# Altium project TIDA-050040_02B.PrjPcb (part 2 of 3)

## Sheet TIDA-050040_Battery.SchDoc
size 431 x 279 mm; Date: Not shown in title block; ApprovedBy: Not shown in title block; CheckedBy: Not shown in title block; Author: Not shown in title block; CompanyName: Not shown in title block; Engineer: Not shown in title block; Organization: Not shown in title block; Address1: Not shown in title block; Address2: Not shown in title block; Address3: Not shown in title block; Address4: Not shown in title block; DocumentNumber: 1; Revision: Use project parameter SCH_Rev; SheetNumber: 2; SheetTotal: 3; PageSetup: Record=PageOptions¦CenterHorizontal=True¦CenterVertical=True¦PrintScale=1.00¦XCorrection=1.00¦YCorrection=1.00¦PrintKind=0¦BorderSize=5000000¦LeftOffset=0¦BottomOffset=0¦Orientation=2¦PaperLength=1000¦PaperWidth=1000¦Scale=100¦PaperSource=15¦PrintQuality=600¦MediaType=1¦DitherType=10¦PaperKind=Letter¦PrintScaleMode=1
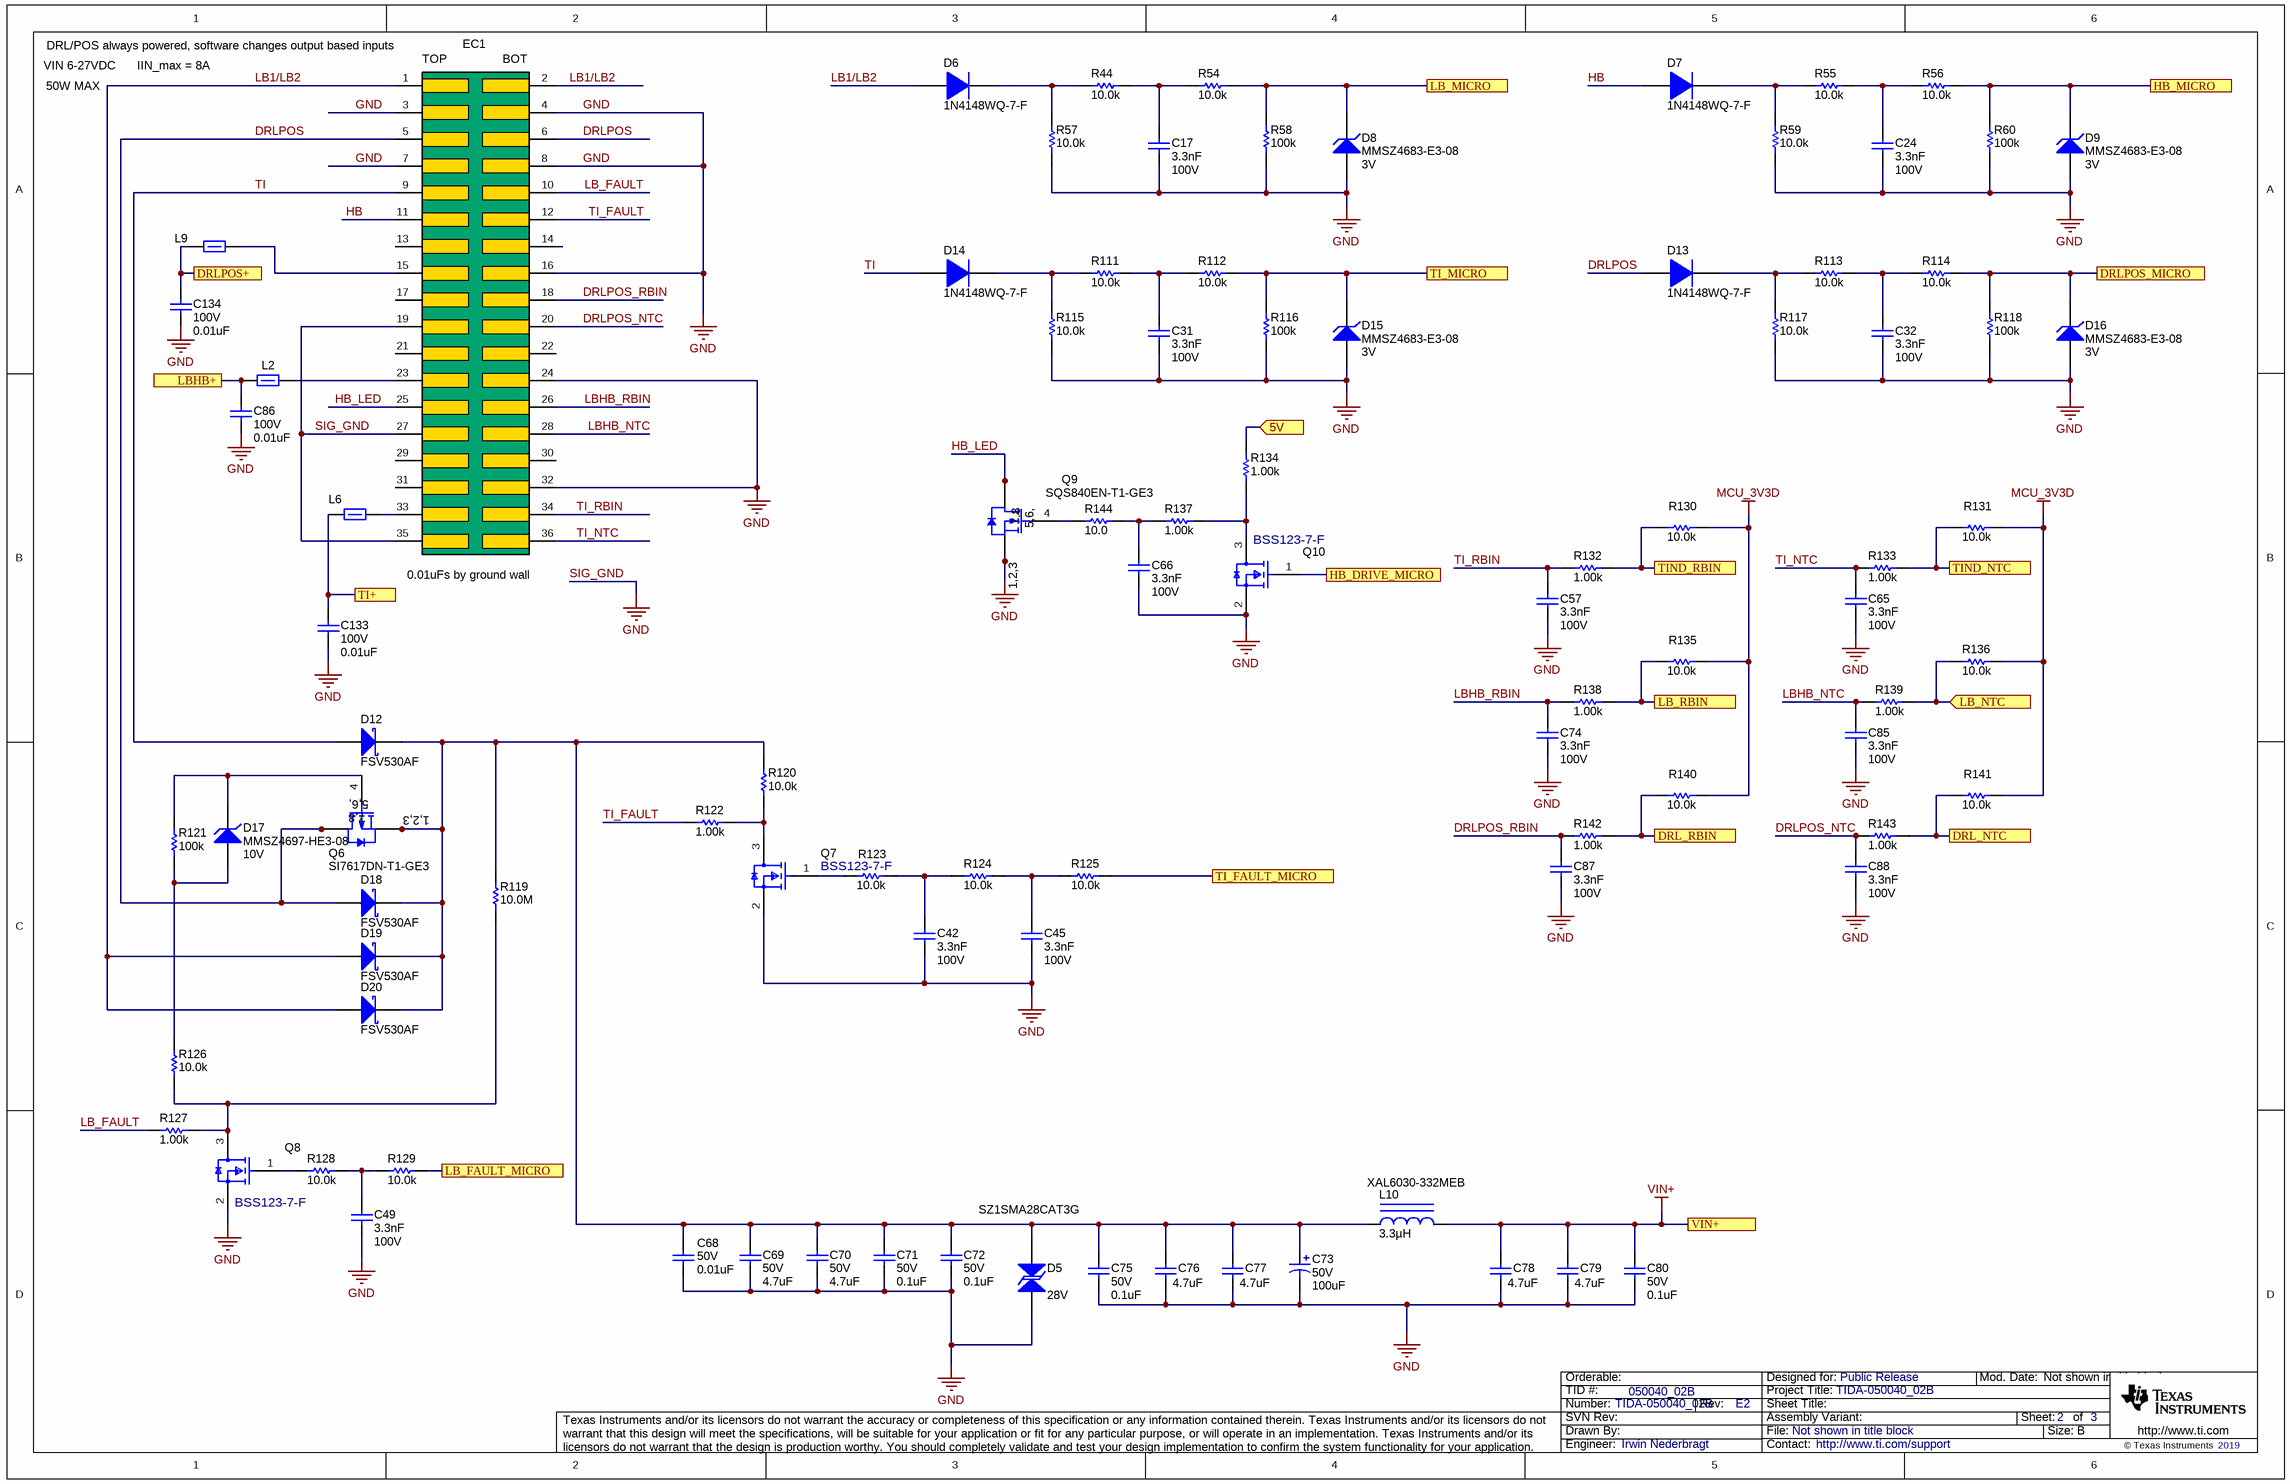
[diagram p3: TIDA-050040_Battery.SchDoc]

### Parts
C17  Cap_F: 3.3nF  VDC_V: 100V  [0603]  (hidden comment: GCM188R72A332KA37D)
C24  Cap_F: 3.3nF  VDC_V: 100V  [0603]  (hidden comment: GCM188R72A332KA37D)
C31  Cap_F: 3.3nF  VDC_V: 100V  [0603]  (hidden comment: GCM188R72A332KA37D)
C32  Cap_F: 3.3nF  VDC_V: 100V  [0603]  (hidden comment: GCM188R72A332KA37D)
C42  Cap_F: 3.3nF  VDC_V: 100V  [0603]  (hidden comment: GCM188R72A332KA37D)
C45  Cap_F: 3.3nF  VDC_V: 100V  [0603]  (hidden comment: GCM188R72A332KA37D)
C49  Cap_F: 3.3nF  VDC_V: 100V  [0603]  (hidden comment: GCM188R72A332KA37D)
C57  Cap_F: 3.3nF  VDC_V: 100V  [0603]  (hidden comment: GCM188R72A332KA37D)
C65  Cap_F: 3.3nF  VDC_V: 100V  [0603]  (hidden comment: GCM188R72A332KA37D)
C66  Cap_F: 3.3nF  VDC_V: 100V  [0603]  (hidden comment: GCM188R72A332KA37D)
C68  VDC_V: 50V  ValueDisplayed: 0.01uF  [0603]  (hidden comment: GCM188R71H103KA37D)
C69  VDC_V: 50V  ValueDisplayed: 4.7uF  [1206_180]  (hidden comment: C3216X7R1H475K160AC)
C70  VDC_V: 50V  ValueDisplayed: 4.7uF  [1206_180]  (hidden comment: C3216X7R1H475K160AC)
C71  VDC_V: 50V  ValueDisplayed: 0.1uF  [0805_HV]  (hidden comment: C0805C104K5RACAUTO)
C72  VDC_V: 50V  ValueDisplayed: 0.1uF  [0805_HV]  (hidden comment: C0805C104K5RACAUTO)
C73  VDC_V: 50V  ValueDisplayed: 100uF  [SM_RADIAL_F]  (hidden comment: EEE-FK1H101P)
C74  Cap_F: 3.3nF  VDC_V: 100V  [0603]  (hidden comment: GCM188R72A332KA37D)
C75  VDC_V: 50V  ValueDisplayed: 0.1uF  [0805_HV]  (hidden comment: C0805C104K5RACAUTO)
C76  ValueDisplayed: 4.7uF  [1206_180]  (hidden comment: C3216X7R1H475K160AC)
C77  ValueDisplayed: 4.7uF  [1206_180]  (hidden comment: C3216X7R1H475K160AC)
C78  ValueDisplayed: 4.7uF  [1206_180]  (hidden comment: C3216X7R1H475K160AC)
C79  ValueDisplayed: 4.7uF  [1206_180]  (hidden comment: C3216X7R1H475K160AC)
C80  VDC_V: 50V  ValueDisplayed: 0.1uF  [0805_HV]  (hidden comment: C0805C104K5RACAUTO)
C85  Cap_F: 3.3nF  VDC_V: 100V  [0603]  (hidden comment: GCM188R72A332KA37D)
C86  VDC_V: 100V  ValueDisplayed: 0.01uF  [0603]  (hidden comment: GRM188R72A103KA01D)
C87  Cap_F: 3.3nF  VDC_V: 100V  [0603]  (hidden comment: GCM188R72A332KA37D)
C88  Cap_F: 3.3nF  VDC_V: 100V  [0603]  (hidden comment: GCM188R72A332KA37D)
C133  VDC_V: 100V  ValueDisplayed: 0.01uF  [0603]  (hidden comment: GRM188R72A103KA01D)
C134  VDC_V: 100V  ValueDisplayed: 0.01uF  [0603]  (hidden comment: GRM188R72A103KA01D)
D5  SZ1SMA28CAT3G  value 28V  [SMA_Bi]
D6  1N4148WQ-7-F  [SOD-123]
D7  1N4148WQ-7-F  [SOD-123]
D8  MMSZ4683-E3-08  value 3V  [SOD-123]
D9  MMSZ4683-E3-08  value 3V  [SOD-123]
D12  FSV530AF  [SMAF]
D13  1N4148WQ-7-F  [SOD-123]
D14  1N4148WQ-7-F  [SOD-123]
D15  MMSZ4683-E3-08  value 3V  [SOD-123]
D16  MMSZ4683-E3-08  value 3V  [SOD-123]
D17  MMSZ4697-HE3-08  value 10V  [SOD-123]
D18  FSV530AF  [SMAF]
D19  FSV530AF  [SMAF]
D20  FSV530AF  [SMAF]
EC1  EDGE_CONN_EBC18DCWN-S371  [Sullins_EDGE_CONN_EBC18DCWN-S371]  (value not drawn)  (no BOM)
L2  742792012  [0805_HV]  (value not drawn)
L6  742792012  [0805_HV]  (value not drawn)
L9  742792012  [0805_HV]  (value not drawn)
L10  ValueDisplayed: 3.3µH  [XAL6030]  (hidden comment: XAL6030-332MEB)
Q6  SI7617DN-T1-GE3  [PowerPAK_1212-8]
Q7  BSS123-7-F  [FP-BSS123-7-F_SOT23-MFG]
Q8  BSS123-7-F  [FP-BSS123-7-F_SOT23-MFG]
Q9  SQS840EN-T1-GE3  [PowerPAK_1212-8]
Q10  BSS123-7-F  [FP-BSS123-7-F_SOT23-MFG]
R44  ValueDisplayed: 10.0k  [0603]  (hidden comment: CRCW060310K0FKEA)
R54  ValueDisplayed: 10.0k  [0603]  (hidden comment: CRCW060310K0FKEA)
R55  ValueDisplayed: 10.0k  [0603]  (hidden comment: CRCW060310K0FKEA)
R56  ValueDisplayed: 10.0k  [0603]  (hidden comment: CRCW060310K0FKEA)
R57  ValueDisplayed: 10.0k  [0603]  (hidden comment: CRCW060310K0FKEA)
R58  ValueDisplayed: 100k  [0603]  (hidden comment: CRCW0603100KFKEA)
R59  ValueDisplayed: 10.0k  [0603]  (hidden comment: CRCW060310K0FKEA)
R60  ValueDisplayed: 100k  [0603]  (hidden comment: CRCW0603100KFKEA)
R111  ValueDisplayed: 10.0k  [0603]  (hidden comment: CRCW060310K0FKEA)
R112  ValueDisplayed: 10.0k  [0603]  (hidden comment: CRCW060310K0FKEA)
R113  ValueDisplayed: 10.0k  [0603]  (hidden comment: CRCW060310K0FKEA)
R114  ValueDisplayed: 10.0k  [0603]  (hidden comment: CRCW060310K0FKEA)
R115  ValueDisplayed: 10.0k  [0603]  (hidden comment: CRCW060310K0FKEA)
R116  ValueDisplayed: 100k  [0603]  (hidden comment: CRCW0603100KFKEA)
R117  ValueDisplayed: 10.0k  [0603]  (hidden comment: CRCW060310K0FKEA)
R118  ValueDisplayed: 100k  [0603]  (hidden comment: CRCW0603100KFKEA)
R119  ValueDisplayed: 10.0M  [0603]  (hidden comment: RC0603FR-0710ML)
R120  ValueDisplayed: 10.0k  [0603]  (hidden comment: CRCW060310K0FKEA)
R121  ValueDisplayed: 100k  [0603]  (hidden comment: CRCW0603100KFKEA)
R122  ValueDisplayed: 1.00k  [0603]  (hidden comment: CRCW06031K00FKEA)
R123  ValueDisplayed: 10.0k  [0603]  (hidden comment: CRCW060310K0FKEA)
R124  ValueDisplayed: 10.0k  [0603]  (hidden comment: CRCW060310K0FKEA)
R125  ValueDisplayed: 10.0k  [0603]  (hidden comment: CRCW060310K0FKEA)
R126  ValueDisplayed: 10.0k  [0603]  (hidden comment: CRCW060310K0FKEA)
R127  ValueDisplayed: 1.00k  [0603]  (hidden comment: CRCW06031K00FKEA)
R128  ValueDisplayed: 10.0k  [0603]  (hidden comment: CRCW060310K0FKEA)
R129  ValueDisplayed: 10.0k  [0603]  (hidden comment: CRCW060310K0FKEA)
R130  ValueDisplayed: 10.0k  [0603]  (hidden comment: CRCW060310K0FKEA)
R131  ValueDisplayed: 10.0k  [0603]  (hidden comment: CRCW060310K0FKEA)
R132  ValueDisplayed: 1.00k  [0603]  (hidden comment: CRCW06031K00FKEA)
R133  ValueDisplayed: 1.00k  [0603]  (hidden comment: CRCW06031K00FKEA)
R134  ValueDisplayed: 1.00k  [0603]  (hidden comment: CRCW06031K00FKEA)
R135  ValueDisplayed: 10.0k  [0603]  (hidden comment: CRCW060310K0FKEA)
R136  ValueDisplayed: 10.0k  [0603]  (hidden comment: CRCW060310K0FKEA)
R137  ValueDisplayed: 1.00k  [0603]  (hidden comment: CRCW06031K00FKEA)
R138  ValueDisplayed: 1.00k  [0603]  (hidden comment: CRCW06031K00FKEA)
R139  ValueDisplayed: 1.00k  [0603]  (hidden comment: CRCW06031K00FKEA)
R140  ValueDisplayed: 10.0k  [0603]  (hidden comment: CRCW060310K0FKEA)
R141  ValueDisplayed: 10.0k  [0603]  (hidden comment: CRCW060310K0FKEA)
R142  ValueDisplayed: 1.00k  [0603]  (hidden comment: CRCW06031K00FKEA)
R143  ValueDisplayed: 1.00k  [0603]  (hidden comment: CRCW06031K00FKEA)
R144  ValueDisplayed: 10.0  [0603]  (hidden comment: CRCW060310R0FKEA)

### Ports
5V, DRL_NTC, DRL_RBIN, DRLPOS+, DRLPOS_MICRO, HB_DRIVE_MICRO, HB_MICRO, LB_FAULT_MICRO, LB_MICRO, LB_NTC, LB_RBIN, LBHB+, TI+, TI_FAULT_MICRO, TI_MICRO, TIND_NTC, TIND_RBIN, VIN+

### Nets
5V: R134.2 ; port 5V
GND: C17.2 C24.2 C31.2 C32.2 C42.2 C45.2 C49.2 C57.2 C65.2 C66.2 C68.2 C69.2 C70.2 C71.2 C72.2 C73.2(-) C74.2 C75.2 C76.2 C77.2 C78.2 C79.2 C80.2 C85.2 C86.2 C87.2 C88.2 C133.2 C134.2 D5.1 D8.2(A) D9.2(A) D15.2(A) D16.2(A) EC1.3 EC1.4 EC1.7 EC1.8 EC1.16 EC1.19 EC1.24 EC1.27 EC1.32 EC1.35 Q7.2(S) Q8.2(S) Q9.1(S) Q9.2(S) Q9.3(S) Q10.2(S) R57.1 R58.1 R59.1 R60.1 R115.1 R116.1 R117.1 R118.1  [also labelled SIG_GND]
MCU_3V3D: R130.2 R131.2 R135.2 R136.2 R140.2 R141.2
VIN+: C78.1 C79.1 C80.1 L10.2 ; port VIN+  [project net VIN]
DRL_NTC: R141.1 R143.2 ; port DRL_NTC
DRLPOS: D13.2(A) D18.2(A) EC1.5 EC1.6 Q6.5(D) Q6.6(D) Q6.7(D) Q6.8(D) Q6.9(D)
DRLPOS+: C134.1 L9.1 ; port DRLPOS+
DRLPOS_MICRO: D16.1(K) R114.2 R118.2 ; port DRLPOS_MICRO
DRLPOS_NTC: C88.1 EC1.20 R143.1
DRLPOS_RBIN: C87.1 EC1.18 R142.1
HB: D7.2(A) EC1.11
HB_DRIVE_MICRO: Q10.1(G) ; port HB_DRIVE_MICRO
HB_LED: EC1.25 Q9.5(D) Q9.6(D) Q9.7(D) Q9.8(D) Q9.9(D)
HB_MICRO: D9.1(K) R56.2 R60.2 ; port HB_MICRO
LB1/LB2: D6.2(A) D19.2(A) D20.2(A) EC1.1 EC1.2
LB_FAULT: EC1.10 R127.1
LB_FAULT_MICRO: R129.2 ; port LB_FAULT_MICRO
LB_MICRO: D8.1(K) R54.2 R58.2 ; port LB_MICRO
LB_NTC: R136.1 R139.2 ; port LB_NTC
LBHB+: C86.1 L2.1 ; port LBHB+
LBHB_NTC: C85.1 EC1.28 R139.1
LBHB_RBIN: C74.1 EC1.26 R138.1
PD5: R135.1 R138.2 ; port LB_RBIN
PD6: R130.1 R132.2 ; port TIND_RBIN
PD7: R140.1 R142.2 ; port DRL_RBIN
TI: D12.2(A) D14.2(A) EC1.9
TI+: C133.1 L6.1 ; port TI+
TI_FAULT: EC1.12 R122.1
TI_FAULT_MICRO: R125.2 ; port TI_FAULT_MICRO
TI_MICRO: D15.1(K) R112.2 R116.2 ; port TI_MICRO
TI_NTC: C65.1 EC1.36 R133.1
TI_RBIN: C57.1 EC1.34 R132.1
TIND_NTC: R131.1 R133.2 ; port TIND_NTC
NetC17_1: C17.1 R44.2 R54.1
NetC24_1: C24.1 R55.2 R56.1
NetC31_1: C31.1 R111.2 R112.1
NetC32_1: C32.1 R113.2 R114.1
NetC42_1: C42.1 R123.2 R124.1
NetC45_1: C45.1 R124.2 R125.1
NetC49_1: C49.1 R128.2 R129.1
NetC66_1: C66.1 R137.1 R144.2
NetC68_1: C68.1 C69.1 C70.1 C71.1 C72.1 C73.1(+) C75.1 C76.1 C77.1 D5.2 D12.1(K) D18.1(K) D19.1(K) D20.1(K) L10.1 Q6.1(S) Q6.2(S) Q6.3(S) R119.2 R120.2
NetD6_1: D6.1(K) R44.1 R57.2
NetD7_1: D7.1(K) R55.1 R59.2
NetD13_1: D13.1(K) R113.1 R117.2
NetD14_1: D14.1(K) R111.1 R115.2
NetD17_1: D17.1(K) Q6.4(G) R121.2
NetD17_2: D17.2(A) R121.1 R126.2
NetEC1_15: EC1.15 L9.2
NetEC1_23: EC1.23 L2.2
NetEC1_33: EC1.33 L6.2
NetQ7_1: Q7.1(G) R123.1
NetQ7_3: Q7.3(D) R120.1 R122.2
NetQ8_1: Q8.1(G) R128.1
NetQ8_3: Q8.3(D) R119.1 R126.1 R127.2
NetQ9_4: Q9.4(G) R144.1
NetQ10_3: Q10.3(D) R134.1 R137.2

Not connected (* = marked no-connect by the designer): EC1 13 14 17 21 22 29 30 31

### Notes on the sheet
- 50W MAX
- VIN 6-27VDC
- IIN_max = 8A
- (near EC1) DRL/POS always powered, software changes output based inputs
- (near EC1) 0.01uFs by ground wall

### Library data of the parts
C17 C24 C31 C32 C42 C45 C49 C57 C65 C66 C74 C85 C87 C88 = CMP-0007148-4: CAP, CERM, 3300 pF, 100 V, +/- 10%, X7R, AEC-Q200 Grade 1, 0603; Manufacturer: MuRata; TaMin_C: -55°C; Polarized: N; SizeAreaWB_mm2: 4.68; Value1: Unknown; U/M: EA; Value: 3300pF; TaMax_C: 125°C; SizeZ_mm: 1; SizeX_mm: 1.6; SizeY_mm: 0.8; SizeArea_mm2: 1.28; CompType: Capacitor; AEC Qualified: Y; AEC Category: Q200
C68 = CMP-0007143-4: CAP, CERM, 0.01 uF, 50 V, +/- 10%, X7R, AEC-Q200 Grade 1, 0603; Manufacturer: MuRata; TaMin_C: -55°C; Polarized: N; SizeAreaWB_mm2: 4.68; Value1: Unknown; U/M: EA; Value: 0.01uF; TaMax_C: 125°C; SizeZ_mm: 1; SizeX_mm: 1.6; SizeY_mm: 0.8; SizeArea_mm2: 1.28; CompType: Capacitor; AEC Qualified: Y; Cap_F: 10nF; AEC Category: Q200
C69 C70 = CMP-0008702-2: CAP, CERM, 4.7 uF, 50 V, +/- 10%, X7R, 1206; Manufacturer: TDK; TaMin_C: -55°C; ESR_ohm: 3.158m; Polarized: N; SizeAreaWB_mm2: 10.92; Value1: 0.003158 ohm; U/M: EA; Value: 4.7uF; TaMax_C: 125°C; SizeZ_mm: 1.8; SizeX_mm: 3.2; SizeY_mm: 1.6; SizeArea_mm2: 5.12; Cap_F: 4.7µF; IRMS_A: 4.08379A; AEC Category: Q200
C71 C72 C75 C80 = CMP-0007725-2: CAP, CERM, 0.1 uF, 50 V, +/- 10%, X7R, AEC-Q200 Grade 0, 0805; Manufacturer: Kemet; TaMin_C: -55°C; Polarized: N; SizeAreaWB_mm2: 6.75; Value1: Unknown; U/M: EA; Value: 0.1uF; TaMax_C: 125°C; SizeZ_mm: 1.45; SizeX_mm: 2; SizeY_mm: 1.25; Cap_Case: 0805; SizeArea_mm2: 2.5; CompType: Capacitor; AEC Qualified: Y; Cap_F: 100nF; AEC Grade: 0; AEC Category: Q200
C73 = CMP-0011177-2: CAP, AL, 100 uF, 50 V, +/- 20%, 0.34 ohm, AEC-Q200 Grade 2, SMD; Manufacturer: Panasonic; TaMin_C: -55°C; ESR_ohm: 3.4d; Polarized: Y; SizeAreaWB_mm2: 123.6; U/M: EA; Value: 100uF; TaMax_C: 105°C; SizeZ_mm: 10.2; SizeX_mm: 10; SizeY_mm: 8.3; Cap_Case: F; SizeArea_mm2: 83; CompType: Capacitor; Cap_F: 100µF; IRMS_A: 3.5dA; AEC Grade: 2; AEC Category: Q200
C76-C79 = CMP-0008702-2: CAP, CERM, 4.7 uF, 50 V, +/- 10%, X7R, 1206; Manufacturer: TDK; TaMin_C: -55°C; ESR_ohm: 3.158m; Polarized: N; SizeAreaWB_mm2: 10.92; Value1: 0.003158 ohm; U/M: EA; Value: 4.7uF; TaMax_C: 125°C; SizeZ_mm: 1.8; SizeX_mm: 3.2; SizeY_mm: 1.6; Value2: 50V; SizeArea_mm2: 5.12; CompType: Capacitor; Cap_F: 4.7µF; IRMS_A: 4.08379A; AEC Category: Q200
C86 C133 C134 = CMP-0007468-5: CAP, CERM, 0.01 uF, 100 V, +/- 10%, X7R, 0603; Manufacturer: MuRata; TaMin_C: -55°C; Polarized: N; SizeAreaWB_mm2: 4.68; Value1: Unknown; U/M: EA; Value: 0.01uF; TaMax_C: 125°C; SizeZ_mm: 1; SizeX_mm: 1.6; SizeY_mm: 0.8; SizeArea_mm2: 1.28; CompType: Capacitor; Cap_F: 10nF; AEC Category: Q200
D5 = CMP-0085086-1: Diode, TVS, Bi, 28 V, 45.4 Vc, 400 W, 8.8 A, AEC-Q101, SMA (non-polarized); Manufacturer: Littelfuse; SizeX_mm: 5.075; Value1: 45.4V; SizeAreaWB_mm2: 32.368125; SizeZ_mm: 2.65; Vbr_Max: 34.37V; Ipp: 8.8A; AEC Category: Q101; Vbr_Min: 31.1V; SizeArea_mm2: 13.068125; AEC Qualified: Y; SizeY_mm: 2.575; Ppk: 400W; RJA_CperW: 250
D6 D7 D13 D14 = CMP-0750148-1: Diode, Switching, 100 V, 0.3 A, AEC-Q101, SOD-123; Manufacturer: Diodes Inc.; Value2: 1.25V; TJmax_C: 150°C; AEC Category: Q101; Value: 100V; SizeAreaWB_mm2: 13.095; SizeArea_mm2: 6.545; SizeX_mm: 3.85; AEC Qualified: Y; Io_A: 3dA; Value1: 0.3A; SizeZ_mm: 1.35; SizeY_mm: 1.7
D8 D9 D15 D16 = CMP-0077593-3: Diode, Zener, 3 V, 500 mW, SOD-123; Manufacturer: Vishay-Semiconductor; SizeAreaWB_mm2: 13.095; Value1: 0.5W; SizeArea_mm2: 6.545; AEC Category: Q101; SizeX_mm: 3.85; SizeY_mm: 1.7; AEC Qualified: N; Power_W: 500mW; RJA_CperW: 340; SizeZ_mm: 1.35
D12 D18-D20 = CMP-0028823-2: Diode, Schottky, 30 V, 5 A, AEC-Q101, SMAF; Manufacturer: Fairchild Semiconductor; Io_A: 5A; Vr_V: 30V; SizeY_mm: 2.5; Green_REACh: Incomplete; SizeArea_mm2: 11.75; SizeZ_mm: 1; AEC Category: Q101; Vf_V: 5.4dV; AEC Qualified: Y; SizeAreaWB_mm2: 19.95; Green_Lifecycle: Not Set; SizeX_mm: 4.7; Value: 30V; Value2: 0.54V; TJmax_C: 150°C
D17 = CMP-0077570-3: Diode, Zener, 10 V, 500 mW, AEC-Q101, SOD-123; Manufacturer: Vishay-Semiconductor; SizeX_mm: 3.85; Power_W: 500mW; RJA_CperW: 340; SizeArea_mm2: 6.545; SizeAreaWB_mm2: 13.095; SizeY_mm: 1.7; AEC Category: Q101; Value1: 0.5W; SizeZ_mm: 1.35; AEC Qualified: Y
EC1 = CMP-0077097-2: Card Edge Footprint, 2.54mm, 18x2; Manufacturer: Sullins Connector Solutions; Pitch_mm: 2.54; CT: True; CNHeader: False
L2 L6 L9 = CMP-0003069-1: Ferrite Bead, 33 ohm @ 100 MHz, 4 A, 0805; Manufacturer: Wurth Elektronik; Ztyp@1GHz_Ohm: 65.242; ZTyp@100MHz_Ohm: 33; SizeAreaWB_mm2: 6.75; DCR_ohm: 8m; Value1: 0.008 ohm; Value: 33 ohm; Imax_A: 4A; SizeZ_mm: 1.45; SizeX_mm: 2; SizeY_mm: 1.25; SizeArea_mm2: 2.5
L10 = CMP-0061017-2: Inductor, Shielded, Composite, 3.3 µH, 8 A, 0.02081 ohm, AEC-Q200 Grade 1, SMD; Manufacturer: Coilcraft; Value: 3.3uH; Imax_A: 8A; Irms: 8A @ 40C rise; Isat: 12.2A @ 30% inductance drop; SizeAreaWB_mm2: 71.5616; SizeArea_mm2: 41.7216; SizeX_mm: 6.36; SizeY_mm: 6.56; SizeZ_mm: 3.1; AEC Category: Q200; AEC Qualified: Y; AEC Grade: 1; Green_Lifecycle: Not Set; Green_REACh: Incomplete
Q6 = CMP-0000123-4: MOSFET, P-CH, -30 V, -13.9 A, PowerPAK 1212; Manufacturer: Vishay-Siliconix; Alternate Manufacturer: None; SizeY_mm: 3.3; ChMode: Enhancement; IdsMax_A: -13.9A; Value1: 0.022; AEC Category: Q101; SizeZ_mm: 1.04; SizeAreaWB_mm2: 18.49; AEC Qualified: N; Value2: 20.5 nC; ChType: P; Rdson45_ohm: 0.0222; Value: -30V; Vgs_V: -25V; SizeArea_mm2: 10.89; QgTyp_nC: 20.5
Q7 Q8 Q10 = CMP-0087176-1: MOSFET N-CH 100V 170MA SOT23-3; Manufacturer: Diodes Incorporated; IdsMax_A: 1.7dA; Vgs_V: 20V; Symbol Name: SYM-BSS123-7-F; ChMode: False; AEC Qualified: No; SizeZ_mm: 1.1mm; Rdson45_ohm: 6
Q9 = CMP-0000752-2: MOSFET, N-CH, 40 V, 12 A, AEC-Q101, PowerPAK 1212; Alternate Manufacturer: None; Manufacturer: Vishay-Siliconix; SizeZ_mm: 1.04; ChType: N; Value2: 15 nC; Value1: 0; VdsMax_V: 40V; SizeX_mm: 3.3; Vgs_V: 20V; AEC Qualified: Y; Value: 40V; Rdson45_ohm: 0.03; SizeArea_mm2: 10.89; AEC Category: Q101; IdsMax_A: 12A; SizeAreaWB_mm2: 18.49; U/M: EA; QgTyp_nC: 15
R44 R54-R56 R111-R114 R123-R125 R128-R131 R135 R136 R140 R141 = CMP-0021998-4: RES, 10.0 k, 1%, 0.1 W, AEC-Q200 Grade 0, 0603; Manufacturer: Vishay-Dale; Power_W: 100mW; TempCo: 100 ppm/C; Value_Code: 10k0; Value: 10.0k; EIA_Code: E96; Res_ohm: 10k; SizeX_mm: 1.6; SizeY_mm: 0.8; SizeZ_mm: 1; Value2: 0.1W; SizeArea_mm2: 1.28; AEC Qualified: Y; VDC_V: 75V; AEC Category: Q200; AEC Grade: 0
R57 R59 R115 R117 R120 R126 = CMP-0021998-4: RES, 10.0 k, 1%, 0.1 W, AEC-Q200 Grade 0, 0603; Manufacturer: Vishay-Dale; Power_W: 100mW; TempCo: 100 ppm/C; Value_Code: 10k0; Value: 10.0k; EIA_Code: E96; Res_ohm: 10k; SizeX_mm: 1.6; SizeY_mm: 0.8; SizeZ_mm: 1; Value2: 0.1W; SizeArea_mm2: 1.28; CompType: Resistor; AEC Qualified: Y; VDC_V: 75V; AEC Category: Q200; AEC Grade: 0
R58 R60 R116 R118 R121 = CMP-0021990-4: RES, 100 k, 1%, 0.1 W, AEC-Q200 Grade 0, 0603; Manufacturer: Vishay-Dale; Power_W: 100mW; TempCo: 100 ppm/C; Value: 100k; EIA_Code: E96; SizeX_mm: 1.6; SizeY_mm: 0.8; SizeZ_mm: 1; Value2: 0.1W; SizeArea_mm2: 1.28; CompType: Resistor; AEC Qualified: Y; VDC_V: 75V; AEC Category: Q200; AEC Grade: 0
R119 = CMP-0022747-4: RES, 10.0 M, 1%, 0.1 W, 0603; Manufacturer: Yageo; Power_W: 100mW; TempCo: 100 ppm/C; Value_Code: 10M0; Value: 10.0Meg; EIA_Code: E96; Res_ohm: 10M; SizeX_mm: 1.6; SizeY_mm: 0.8; SizeZ_mm: 1; Value2: 0.1W; SizeArea_mm2: 1.28; CompType: Resistor; AEC Qualified: N; VDC_V: 75V; AEC Category: Q200; SizeAreaWB_mm2: 4.68
R122 R127 R132 R133 R137-R139 R142 R143 = CMP-0022109-5: RES, 1.00 k, 1%, 0.1 W, AEC-Q200 Grade 0, 0603; Manufacturer: Vishay-Dale; Power_W: 100mW; TempCo: 100 ppm/C; Value_Code: 1k00; Value: 1.00k; EIA_Code: E96; Res_ohm: 1k; SizeX_mm: 1.6; SizeY_mm: 0.8; SizeZ_mm: 1; Value2: 0.1W; SizeArea_mm2: 1.28; AEC Qualified: Y; VDC_V: 75V; AEC Category: Q200; AEC Grade: 0
R134 = CMP-0022109-5: RES, 1.00 k, 1%, 0.1 W, AEC-Q200 Grade 0, 0603; Manufacturer: Vishay-Dale; Power_W: 100mW; TempCo: 100 ppm/C; Value_Code: 1k00; Value: 1.00k; EIA_Code: E96; Res_ohm: 1k; SizeX_mm: 1.6; SizeY_mm: 0.8; SizeZ_mm: 1; Value2: 0.1W; SizeArea_mm2: 1.28; CompType: Resistor; AEC Qualified: Y; VDC_V: 75V; AEC Category: Q200; AEC Grade: 0
R144 = CMP-0022003-4: RES, 10.0, 1%, 0.1 W, AEC-Q200 Grade 0, 0603; Manufacturer: Vishay-Dale; Power_W: 100mW; TempCo: 100 ppm/C; Value_Code: 10R0; Value: 10.0; EIA_Code: E96; Res_ohm: 10; SizeX_mm: 1.6; SizeY_mm: 0.8; SizeZ_mm: 1; Value2: 0.1W; SizeArea_mm2: 1.28; AEC Qualified: Y; VDC_V: 75V; AEC Category: Q200; AEC Grade: 0

## Sheet TIDA-050040_MSP432E4x.SchDoc: Bucks 05-08
size 431 x 279 mm; Date: Not shown in title block; ApprovedBy: Not shown in title block; CheckedBy: Not shown in title block; Author: Not shown in title block; CompanyName: Not shown in title block; DrawnBy: Kerry Murphy; Engineer: Not shown in title block; Organization: Not shown in title block; Address1: Not shown in title block; Address2: Not shown in title block; Address3: Not shown in title block; Address4: Not shown in title block; DocumentNumber: 2; Revision: Use project parameter SCH_Rev; SheetNumber: 2; SheetTotal: 10; PageSetup: Record=PageOptions¦CenterHorizontal=True¦CenterVertical=True¦PrintScale=0.98¦XCorrection=1.00¦YCorrection=1.00¦PrintKind=0¦BorderSize=5000000¦LeftOffset=0¦BottomOffset=0¦Orientation=2¦PaperLength=1000¦PaperWidth=1000¦Scale=100¦PaperSource=15¦PrintQuality=600¦MediaType=1¦DitherType=10¦PrintScaleMode=1¦PaperKind=11 x 17¦PaperIndex=119
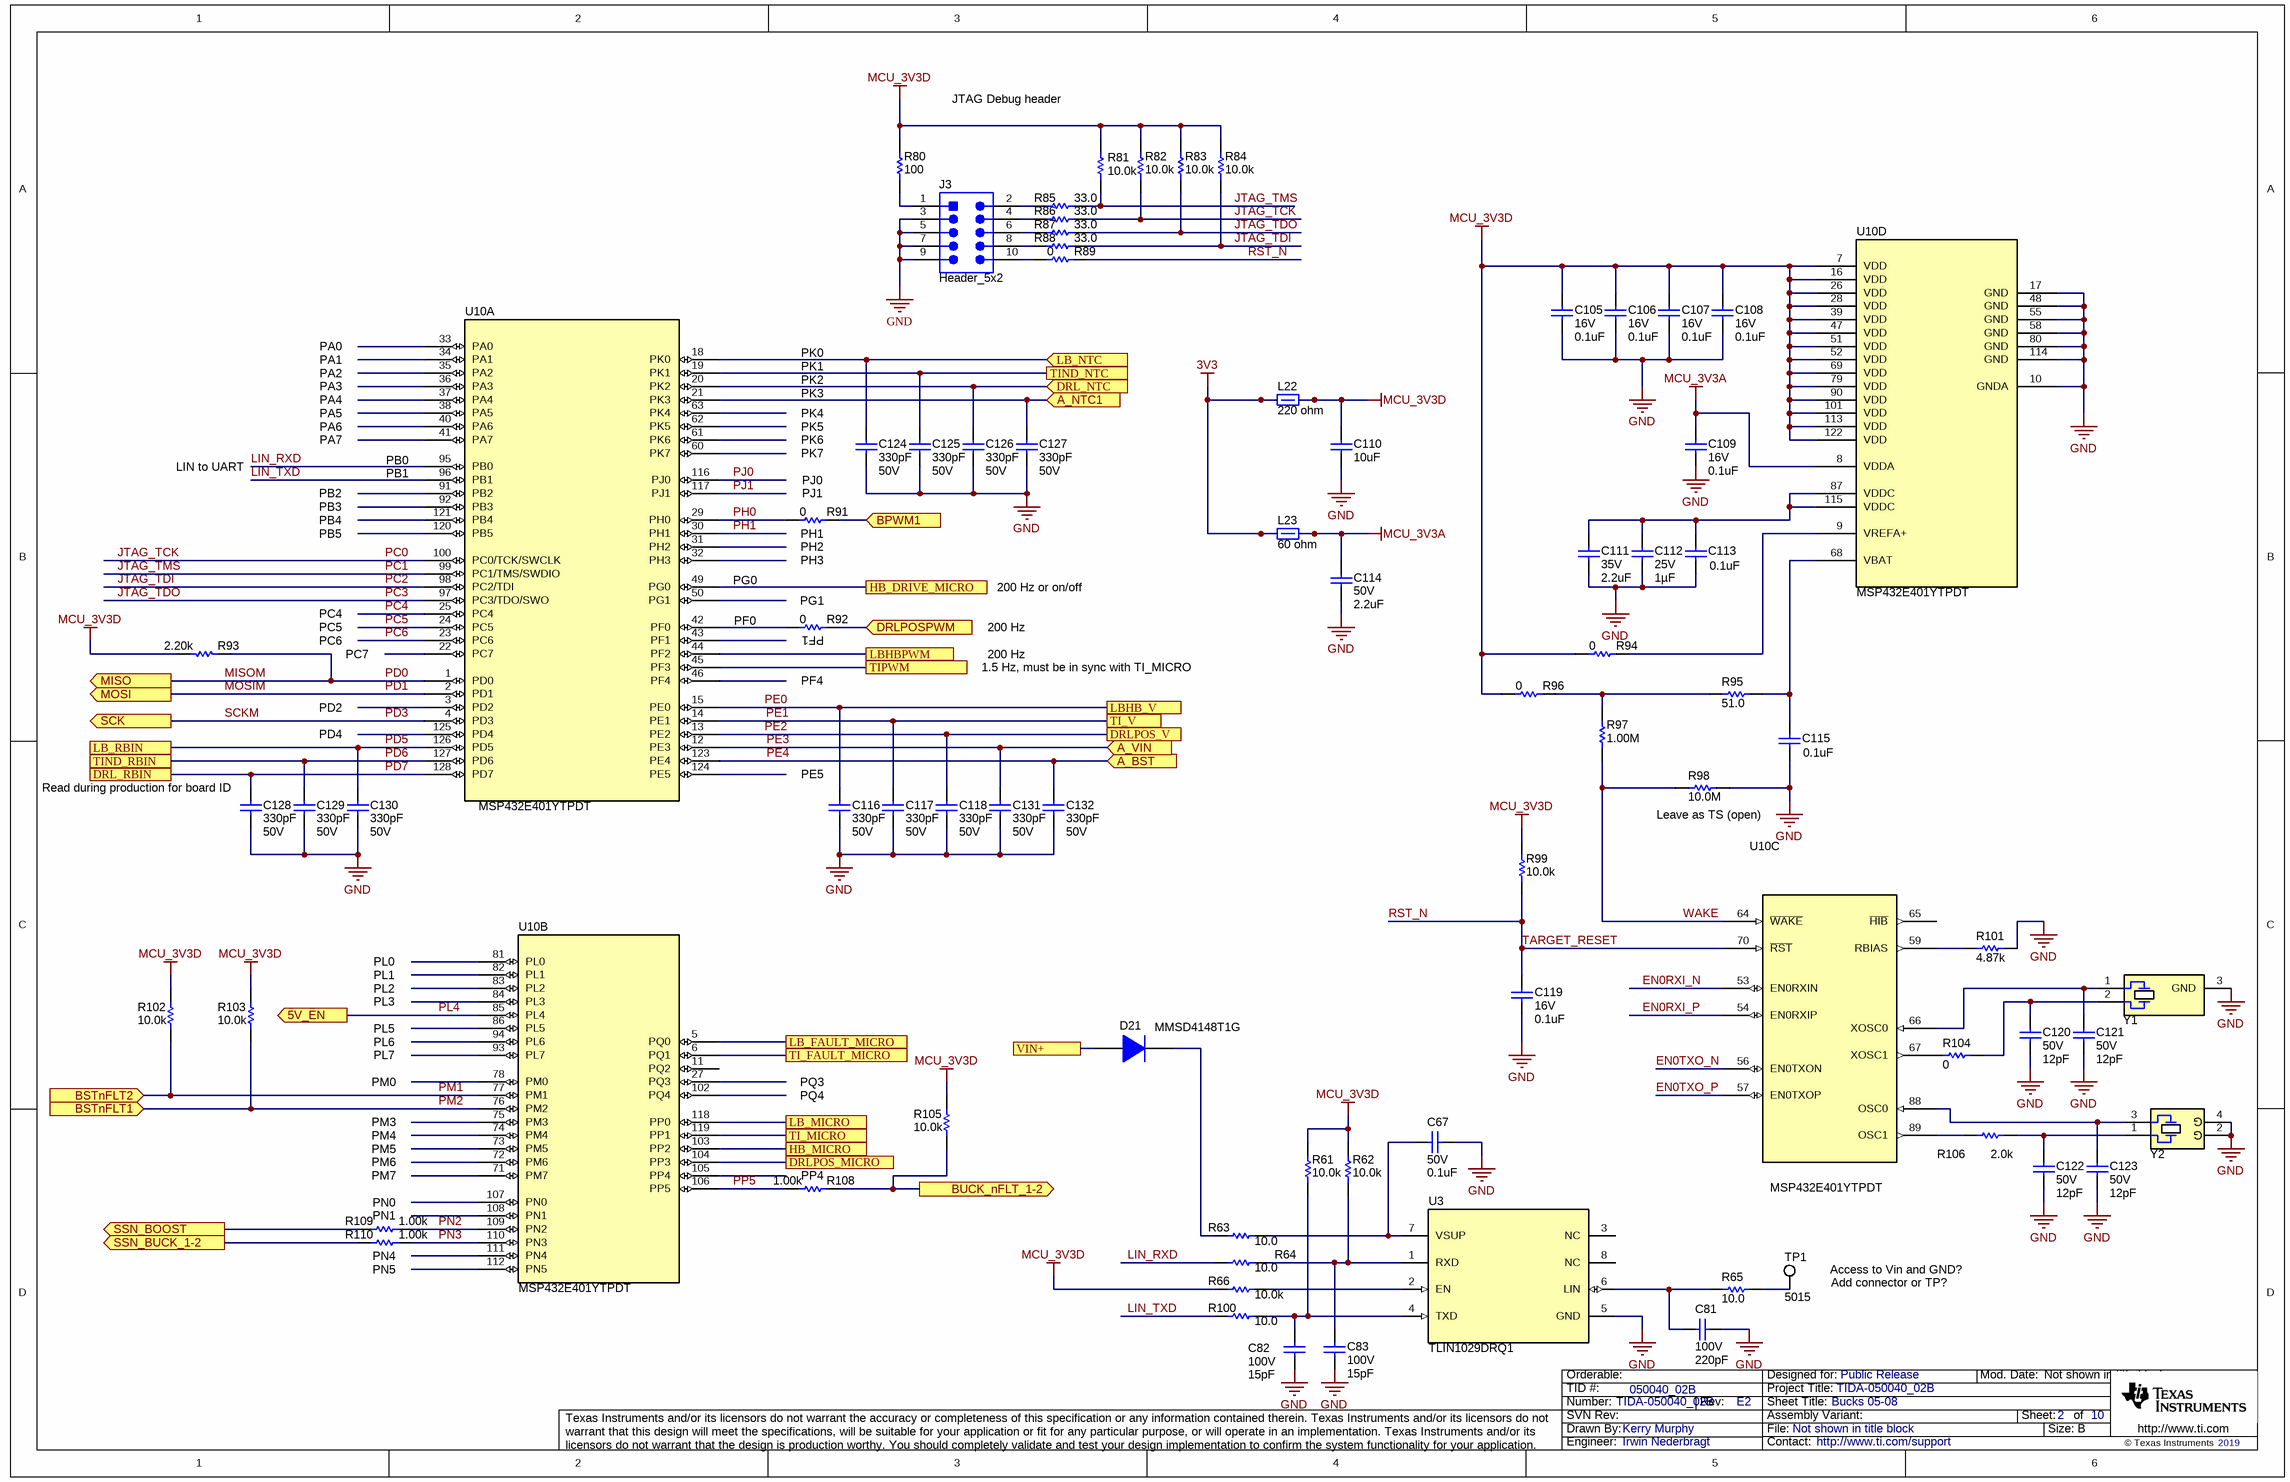
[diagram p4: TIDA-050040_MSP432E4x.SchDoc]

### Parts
C67  VDC_V: 50V  ValueDisplayed: 0.1uF  [0805_HV]  (hidden comment: C0805C104K5RACAUTO)
C81  VDC_V: 100V  ValueDisplayed: 220pF  [0603]  (hidden comment: GCM1885C2A221JA16D)
C82  VDC_V: 100V  ValueDisplayed: 15pF  [0603]  (hidden comment: GCM1885C2A150JA16D)
C83  VDC_V: 100V  ValueDisplayed: 15pF  [0603]  (hidden comment: GCM1885C2A150JA16D)
C105  VDC_V: 16V  ValueDisplayed: 0.1uF  [0402]  (hidden comment: GRM155R71C104KA88D)
C106  VDC_V: 16V  ValueDisplayed: 0.1uF  [0402]  (hidden comment: GRM155R71C104KA88D)
C107  VDC_V: 16V  ValueDisplayed: 0.1uF  [0402]  (hidden comment: GRM155R71C104KA88D)
C108  VDC_V: 16V  ValueDisplayed: 0.1uF  [0402]  (hidden comment: GRM155R71C104KA88D)
C109  VDC_V: 16V  ValueDisplayed: 0.1uF  [0402]  (hidden comment: GRM155R71C104KA88D)
C110  ValueDisplayed: 10uF  [1206_180]  (hidden comment: Capacitor)
C111  VDC_V: 35V  ValueDisplayed: 2.2uF  [0603]  (hidden comment: GRM188R6YA225KA12D)
C112  VDC_V: 25V  ValueDisplayed: 1µF  [0402]  (hidden comment: GRM155R61E105KE11D)
C113  ValueDisplayed: 0.1uF  [0402]  (hidden comment: GRM155R71C104KA88D)
C114  VDC_V: 50V  ValueDisplayed: 2.2uF  [1206_180]  (hidden comment: GCM31CR71H225KA55L)
C115  ValueDisplayed: 0.1uF  [0402]  (hidden comment: GRM155R71C104KA88D)
C116  Cap_F: 330pF  VDC_V: 50V  [0603_HV]  (hidden comment: C0603C331K5RACTU)
C117  Cap_F: 330pF  VDC_V: 50V  [0603_HV]  (hidden comment: C0603C331K5RACTU)
C118  Cap_F: 330pF  VDC_V: 50V  [0603_HV]  (hidden comment: C0603C331K5RACTU)
C119  VDC_V: 16V  ValueDisplayed: 0.1uF  [0402]  (hidden comment: GRM155R71C104KA88D)
C120  VDC_V: 50V  ValueDisplayed: 12pF  [0402]  (hidden comment: GRM1555C1H120JA01D)
C121  VDC_V: 50V  ValueDisplayed: 12pF  [0402]  (hidden comment: GRM1555C1H120JA01D)
C122  VDC_V: 50V  ValueDisplayed: 12pF  [0402]  (hidden comment: GRM1555C1H120JA01D)
C123  VDC_V: 50V  ValueDisplayed: 12pF  [0402]  (hidden comment: GRM1555C1H120JA01D)
C124  Cap_F: 330pF  VDC_V: 50V  [0603_HV]  (hidden comment: C0603C331K5RACTU)
C125  Cap_F: 330pF  VDC_V: 50V  [0603_HV]  (hidden comment: C0603C331K5RACTU)
C126  Cap_F: 330pF  VDC_V: 50V  [0603_HV]  (hidden comment: C0603C331K5RACTU)
C127  Cap_F: 330pF  VDC_V: 50V  [0603_HV]  (hidden comment: C0603C331K5RACTU)
C128  Cap_F: 330pF  VDC_V: 50V  [0603_HV]  (hidden comment: C0603C331K5RACTU)
C129  Cap_F: 330pF  VDC_V: 50V  [0603_HV]  (hidden comment: C0603C331K5RACTU)
C130  Cap_F: 330pF  VDC_V: 50V  [0603_HV]  (hidden comment: C0603C331K5RACTU)
C131  Cap_F: 330pF  VDC_V: 50V  [0603_HV]  (hidden comment: C0603C331K5RACTU)
C132  Cap_F: 330pF  VDC_V: 50V  [0603_HV]  (hidden comment: C0603C331K5RACTU)
D21  MMSD4148T1G  [SOD-123]
J3  Header_5x2  [Samtec_FTSH-105-01-x-DV]
L22  value 220 ohm  [0805_HV]  (hidden comment: Ferrite_Bead)
L23  value 60 ohm  [0805_HV]  (hidden comment: Ferrite_Bead)
R61  ValueDisplayed: 10.0k  [0603]  (hidden comment: CRCW060310K0FKEA)
R62  ValueDisplayed: 10.0k  [0603]  (hidden comment: CRCW060310K0FKEA)
R63  ValueDisplayed: 10.0  [0603]  (hidden comment: CRCW060310R0FKEA)
R64  ValueDisplayed: 10.0  [0603]  (hidden comment: CRCW060310R0FKEA)
R65  ValueDisplayed: 10.0  [0603]  (hidden comment: CRCW060310R0FKEA)
R66  ValueDisplayed: 10.0k  [0603]  (hidden comment: CRCW060310K0FKEA)
R80  ValueDisplayed: 100  [0402]  (hidden comment: RMCF0402JT100R)
R81  ValueDisplayed: 10.0k  [0402]  (hidden comment: RMCF0402FT10K0)
R82  ValueDisplayed: 10.0k  [0402]  (hidden comment: RMCF0402FT10K0)
R83  ValueDisplayed: 10.0k  [0402]  (hidden comment: RMCF0402FT10K0)
R84  ValueDisplayed: 10.0k  [0402]  (hidden comment: RMCF0402FT10K0)
R85  ValueDisplayed: 33.0  [0402]  (hidden comment: RMCF0402FT33R0)
R86  ValueDisplayed: 33.0  [0402]  (hidden comment: RMCF0402FT33R0)
R87  ValueDisplayed: 33.0  [0402]  (hidden comment: RMCF0402FT33R0)
R88  ValueDisplayed: 33.0  [0402]  (hidden comment: RMCF0402FT33R0)
R89  ValueDisplayed: 0  [0603_HV]  (hidden comment: Resistor)
R91  ValueDisplayed: 0  [0603_HV]  (hidden comment: Resistor)
R92  ValueDisplayed: 0  [0603_HV]  (hidden comment: Resistor)
R93  ValueDisplayed: 2.20k  [0603_HV]  (hidden comment: Resistor)
R94  ValueDisplayed: 0  [0603_HV]  (hidden comment: Resistor)
R95  ValueDisplayed: 51.0  [0603]  (hidden comment: RC0603FR-0751RL)
R96  ValueDisplayed: 0  [0603_HV]  (hidden comment: Resistor)
R97  ValueDisplayed: 1.00M  [0603]  (hidden comment: CRCW06031M00FKEA)
R98  ValueDisplayed: 10.0M  [0603]  (hidden comment: RC0603FR-0710ML)
R99  ValueDisplayed: 10.0k  [0603]  (hidden comment: RMCF0603FT10K0)
R100  ValueDisplayed: 10.0  [0603]  (hidden comment: CRCW060310R0FKEA)
R101  ValueDisplayed: 4.87k  [0603]  (hidden comment: CRCW06034K87FKEA)
R102  ValueDisplayed: 10.0k  [0603]  (hidden comment: RMCF0603FT10K0)
R103  ValueDisplayed: 10.0k  [0603]  (hidden comment: RMCF0603FT10K0)
R104  ValueDisplayed: 0  [0402]  (hidden comment: RC0402JR-070RL)
R105  ValueDisplayed: 10.0k  [0603]  (hidden comment: RMCF0603FT10K0)
R106  ValueDisplayed: 2.0k  [0402]  (hidden comment: CRCW04022K00JNED)
R108  ValueDisplayed: 1.00k  [0603_HV]  (hidden comment: CRCW06031K00FKEA)
R109  ValueDisplayed: 1.00k  [0603_HV]  (hidden comment: CRCW06031K00FKEA)
R110  ValueDisplayed: 1.00k  [0603_HV]  (hidden comment: CRCW06031K00FKEA)
TP1  5015  [Testpoint_Keystone_Miniature]
U3  TLIN1029DRQ1  [D0008A_N]
U10  MSP432E401YTPDT  [PDT0128A]  (parts A,B,C,D of 4)
Y1  CMR200T-32.768KDZY-UT  [CFM_CMR200T]  (value not drawn)
Y2  NX3225GA-25.000M-STD-CRG-2  [NDK_NX3225GA]  (value not drawn)

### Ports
5V_EN, A_BST, A_NTC1 (in), A_VIN, BPWM1, BSTnFLT1, BSTnFLT2, BUCK_nFLT_1-2, DRL_NTC, DRL_RBIN, DRLPOS_MICRO, DRLPOS_V, DRLPOSPWM, HB_DRIVE_MICRO, HB_MICRO, LB_FAULT_MICRO, LB_MICRO, LB_NTC, LB_RBIN, LBHB_V, LBHBPWM, MISO, MOSI, SCK, SSN_BOOST, SSN_BUCK_1-2, TI_FAULT_MICRO, TI_MICRO, TI_V, TIND_NTC, TIND_RBIN, TIPWM, VIN+

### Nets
3V3: L22.1 L23.1
GND: C67.1 C81.1 C82.2 C83.2 C105.2 C106.2 C107.2 C108.2 C109.2 C110.2 C111.2 C112.2 C113.2 C114.2 C115.2 C116.2 C117.2 C118.2 C119.2 C120.2 C121.2 C122.2 C123.2 C124.2 C125.2 C126.2 C127.2 C128.2 C129.2 C130.2 C131.2 C132.2 J3.3 J3.5 J3.7 J3.9 R98.2 R101.2 U3.5(GND) U10.10(GNDA) U10.17(GND) U10.48(GND) U10.55(GND) U10.58(GND) U10.80(GND) U10.114(GND) Y1.3(GND) Y2.2(GND) Y2.4(GND)
MCU_3V3A: C109.1 C114.1 L23.2 U10.8(VDDA)
MCU_3V3D: C105.1 C106.1 C107.1 C108.1 C110.1 L22.2 R61.2 R62.2 R66.1 R80.2 R81.2 R82.2 R83.2 R84.2 R93.2 R94.1 R96.1 R99.1 R102.2 R103.2 R105.2 U10.7(VDD) U10.16(VDD) U10.26(VDD) U10.28(VDD) U10.39(VDD) U10.47(VDD) U10.51(VDD) U10.52(VDD) U10.69(VDD) U10.79(VDD) U10.90(VDD) U10.101(VDD) U10.113(VDD) U10.122(VDD)
VIN: D21.2(A) ; port VIN+
A_NTC1: C127.1 U10.21(PK3) ; port A_NTC1
BPWM1: R91.2 ; port BPWM1
BUCK_nFLT_1-2: R105.1 R108.2 ; port BUCK_nFLT_1-2
DRL_NTC: C126.1 U10.20(PK2) ; port DRL_NTC
DRLPOS_MICRO: U10.104(PP3) ; port DRLPOS_MICRO
DRLPOSPWM: R92.2 ; port DRLPOSPWM
EN0RXI_N: U10.53(EN0RXIN)
EN0RXI_P: U10.54(EN0RXIP)
EN0TXO_N: U10.56(EN0TXON)
EN0TXO_P: U10.57(EN0TXOP)
HB_DRIVE_MICRO: U10.49(PG0) ; port HB_DRIVE_MICRO
HB_MICRO: U10.103(PP2) ; port HB_MICRO
JTAG_TCK: R82.1 R86.2 U10.100(PC0/TCK/SWCLK)  [also labelled PC0]
JTAG_TDI: R84.1 R88.2 U10.98(PC2/TDI)  [also labelled PC2]
JTAG_TDO: R83.1 R87.2 U10.97(PC3/TDO/SWO)  [also labelled PC3]
JTAG_TMS: R81.1 R85.2 U10.99(PC1/TMS/SWDIO)  [also labelled PC1]
LB_FAULT_MICRO: U10.5(PQ0) ; port LB_FAULT_MICRO
LB_MICRO: U10.118(PP0) ; port LB_MICRO
LB_NTC: C124.1 U10.18(PK0) ; port LB_NTC
LBHBPWM: U10.44(PF2) ; port LBHBPWM
LIN_RXD: R64.1 U10.95(PB0)
LIN_TXD: R100.1 U10.96(PB1)
MISOM: R93.1 U10.1(PD0) ; port MISO  [also labelled PD0]
MOSIM: U10.2(PD1) ; port MOSI  [also labelled PD1]
PC4: U10.25(PC4)
PC5: U10.24(PC5)
PC6: U10.23(PC6)
PD3: U10.4(PD3) ; port SCK  [also labelled SCKM]
PD5: C130.1 U10.126(PD5) ; port LB_RBIN
PD6: C129.1 U10.127(PD6) ; port TIND_RBIN
PD7: C128.1 U10.128(PD7) ; port DRL_RBIN
PE0: C116.1 U10.15(PE0) ; port LBHB_V
PE1: C117.1 U10.14(PE1) ; port TI_V
PE2: C118.1 U10.13(PE2) ; port DRLPOS_V
PE3: C131.1 U10.12(PE3) ; port A_VIN
PE4: C132.1 U10.123(PE4) ; port A_BST
PH0: R91.1 U10.29(PH0)
PH1: U10.30(PH1)
PJ0: U10.116(PJ0)
PJ1: U10.117(PJ1)
PL4: U10.85(PL4) ; port 5V_EN
PM1: R102.1 U10.77(PM1) ; port BSTnFLT2
PM2: R103.1 U10.76(PM2) ; port BSTnFLT1
PN2: R109.2 U10.109(PN2)
PN3: R110.2 U10.110(PN3)
PP5: R108.1 U10.106(PP5)
RST_N: C119.1 R89.2 R99.2 U10.70(~{RST})  [also labelled TARGET_RESET]
SSN_BOOST: R109.1 ; port SSN_BOOST
SSN_BUCK_1-2: R110.1 ; port SSN_BUCK_1-2
TI_FAULT_MICRO: U10.6(PQ1) ; port TI_FAULT_MICRO
TI_MICRO: U10.119(PP1) ; port TI_MICRO
TIND_NTC: C125.1 U10.19(PK1) ; port TIND_NTC
TIPWM: U10.45(PF3) ; port TIPWM
WAKE: R97.1 R98.1 U10.64(~{WAKE})
NetC67_2: C67.2 R63.2 U3.7(VSUP)
NetC81_2: C81.2 R65.1 U3.6(LIN)
NetC82_1: C82.1 R61.1 R100.2 U3.4(TXD)
NetC83_1: C83.1 R62.1 R64.2 U3.1(RXD)
NetC111_1: C111.1 C112.1 C113.1 U10.87(VDDC) U10.115(VDDC)
NetC115_1: C115.1 R95.2 U10.68(VBAT)
NetC120_1: C120.1 R104.2 Y1.2
NetC121_1: C121.1 U10.66(XOSC0) Y1.1
NetC122_1: C122.1 R106.2 Y2.1
NetC123_1: C123.1 U10.88(OSC0) Y2.3
NetD21_1: D21.1(K) R63.1
NetJ3_1: J3.1 R80.1
NetJ3_2: J3.2 R85.1
NetJ3_4: J3.4 R86.1
NetJ3_6: J3.6 R87.1
NetJ3_8: J3.8 R88.1
NetJ3_10: J3.10 R89.1
NetR65_2: R65.2 TP1.1
NetR66_2: R66.2 U3.2(EN)
NetR92_1: R92.1 U10.42(PF0)
NetR94_2: R94.2 U10.9(VREFA+)
NetR95_1: R95.1 R96.2 R97.2
NetR101_1: R101.1 U10.59(RBIAS)
NetR104_1: R104.1 U10.67(XOSC1)
NetR106_1: R106.1 U10.89(OSC1)

Not connected (* = marked no-connect by the designer): U3 3(NC) 8(NC); U10 3(PD2) 11(PQ2) 22(PC7) 27(PQ3) 31(PH2) 32(PH3) 33(PA0) 34(PA1) 35(PA2) 36(PA3) 37(PA4) 38(PA5) 40(PA6) 41(PA7) 43(PF1) 46(PF4) 50(PG1) 60(PK7) 61(PK6) 62(PK5) 63(PK4) 65(~{HIB}) 71(PM7) 72(PM6) 73(PM5) 74(PM4) 75(PM3) 78(PM0) 81(PL0) 82(PL1) 83(PL2) 84(PL3) 86(PL5) 91(PB2) 92(PB3) 93(PL7) 94(PL6) 102(PQ4) 105(PP4) 107(PN0) 108(PN1) 111(PN4) 112(PN5) 120(PB5) 121(PB4) 124(PE5) 125(PD4)

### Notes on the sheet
- JTAG Debug header
- PA1
- PA0
- PK1
- PK0
- PA2
- PA3
- PA4
- PA5
- PA6
- PA7
- (near C124) PK6
- (near C124) PK5
- (near C124) PK4
- PK3
- PK2
- LIN to UART
- PB2
- PB1
- PB0
- (near R91) PJ1
- PJ0
- PK7
- PB3
- PB4
- PB5
- (near R91) PH2
- (near R91) PH3
- (near R91) PH1
- PC4
- PC5
- PF0
- PG0
- (near R92) PG1
- 200 Hz
- 200 Hz or on/off
- PD2
- PC6
- PC7
- (near R92) PF4
- (near R92) PF1
- 1.5 Hz, must be in sync with TI_MICRO
- PD4
- (near C128) Read during production for board ID
- (near C116) PE5
- (near R98) Leave as TS (open)
- PL0
- PL1
- PL2
- PL3
- PL5
- PM0
- PL6
- PL7
- PQ3
- PQ4
- PM3
- PM4
- PM5
- PM6
- PM7
- PN0
- (near R109) PN1
- (near R108) PP4
- (near R110) PN4
- PN5
- (near TP1) Add connector or TP?
- (near TP1) Access to Vin and GND?

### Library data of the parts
C67 = CMP-0007725-2: as C71 on sheet TIDA-050040_Battery
C81 = CMP-0860912-1: CAP, CERM, 220 pF, 100 V,+/- 5%, C0G/NP0, AEC-Q200 Grade 1, 0603; Manufacturer: MuRata; SizeArea_mm2: 1.28; CompType: Capacitor; AEC Grade: 1; SizeAreaWB_mm2: 4.68; Value: 220pF; U/M: EA; TaMax_C: 125°C; TaMin_C: -55°C; SizeY_mm: 0.8; AEC Qualified: Y; AEC Category: Q200; Polarized: N; SizeX_mm: 1.6
C82 C83 = CMP-0080704-2: CAP, CERM, 15 pF, 100 V,+/- 5%, C0G/NP0, AEC-Q200 Grade 1, 0603; Manufacturer: MuRata; SizeAreaWB_mm2: 4.68; SizeArea_mm2: 1.28; AEC Qualified: Y; AEC Category: Q200; Value: 15pF; TaMax_C: 125°C; SizeZ_mm: 1; Polarized: N; TaMin_C: -55°C; SizeY_mm: 0.8; U/M: EA; CompType: Capacitor; SizeX_mm: 1.6
C105-C109 C119 = CMP-0006641-2: CAP, CERM, 0.1 uF, 16 V, +/- 10%, X7R, 0402; Manufacturer: MuRata; TaMin_C: -55°C; Polarized: N; SizeAreaWB_mm2: 3; Value1: Unknown; U/M: EA; Value: 0.1uF; TaMax_C: 125°C; SizeZ_mm: 0.6; SizeX_mm: 1; SizeY_mm: 0.5; Cap_F: 100nF; AEC Category: Q200
C110 = CMP-0008965-2: CAP, CERM, 10 uF, 25 V, +/- 10%, X7R, 1206; PartNumber: GRM31CR71E106KA12L; Manufacturer: MuRata; Polarized: N; Value: 10uF; U/M: EA; Cap_F: 10µF; Value1: Unknown; VDC_V: 25V; TaMin_C: -55°C; TaMax_C: 125°C; Cap_Case: 2220; SizeArea_mm2: 5.12; SizeAreaWB_mm2: 10.92; SizeX_mm: 3.2; SizeY_mm: 1.6; SizeZ_mm: 1.8; AEC Category: Q200
C111 = CMP-0007356-5: CAP, CERM, 2.2 uF, 35 V, +/- 10%, X5R, 0603; Manufacturer: MuRata; TaMin_C: -55°C; Polarized: N; SizeAreaWB_mm2: 4.68; Value1: Unknown; U/M: EA; Value: 2.2uF; TaMax_C: 85°C; SizeZ_mm: 1; SizeX_mm: 1.6; SizeY_mm: 0.8; SizeArea_mm2: 1.28; CompType: Capacitor; Cap_F: 2.2µF; AEC Category: Q200
C112 = CMP-0086061-1: CAP, CERM, 1 µF, 25 V,+/- 10%, X5R, 0402; Manufacturer: MuRata; SizeY_mm: 0.5; TaMin_C: -55°C; Polarized: N; AEC Category: Q200; CompType: Capacitor; SizeX_mm: 1; SizeAreaWB_mm2: 3; SizeZ_mm: 0.6; Value: 1uF; TaMax_C: 85°C; U/M: EA
C113 C115 = CMP-0006641-2: CAP, CERM, 0.1 uF, 16 V, +/- 10%, X7R, 0402; Manufacturer: MuRata; TaMin_C: -55°C; Polarized: N; SizeAreaWB_mm2: 3; Value1: Unknown; U/M: EA; Value: 0.1uF; TaMax_C: 125°C; SizeZ_mm: 0.6; SizeX_mm: 1; SizeY_mm: 0.5; Value2: 16V; CompType: Capacitor; Cap_F: 100nF; AEC Category: Q200
C114 = CMP-0008814-2: CAP, CERM, 2.2 uF, 50 V, +/- 10%, X7R, AEC-Q200 Grade 1, 1206; Manufacturer: MuRata; TaMin_C: -55°C; Polarized: N; SizeAreaWB_mm2: 10.92; Value1: Unknown; U/M: EA; Value: 2.2uF; TaMax_C: 125°C; SizeZ_mm: 1.8; SizeX_mm: 3.2; SizeY_mm: 1.6; Cap_Case: 1206; SizeArea_mm2: 5.12; CompType: Capacitor; AEC Qualified: Y; Cap_F: 2.2µF; AEC Grade: 1; AEC Category: Q200
C116-C118 C124-C132 = CMP-0006921-4: CAP, CERM, 330 pF, 50 V, +/- 10%, X7R, 0603; Manufacturer: Kemet; TaMin_C: -55°C; Polarized: N; SizeAreaWB_mm2: 4.68; Value1: Unknown; U/M: EA; Value: 330pF; TaMax_C: 125°C; SizeZ_mm: 1; SizeX_mm: 1.6; SizeY_mm: 0.8; Cap_Case: 0603; SizeArea_mm2: 1.28; CompType: Capacitor; AEC Category: Q200
C120-C123 = CMP-0006415-2: CAP, CERM, 12 pF, 50 V, +/- 5%, C0G/NP0, 0402; Manufacturer: MuRata; TaMin_C: -55°C; Polarized: N; SizeAreaWB_mm2: 3; Value1: Unknown; U/M: EA; Value: 12pF; TaMax_C: 125°C; SizeZ_mm: 0.6; SizeX_mm: 1; SizeY_mm: 0.5; AEC Category: Q200
D21 = CMP-0029032-2: Diode, Switching, 100 V, 0.2 A, SOD-123; Manufacturer: ON Semiconductor; Value: 100V; SizeY_mm: 1.7; Io_A: 2dA; SizeAreaWB_mm2: 13.095; SizeArea_mm2: 6.545; Vf_V: 1V; TJmax_C: 150°C; SizeX_mm: 3.85; SizeZ_mm: 1.35; Value1: 0.2A; Green_Lifecycle: Active; AEC Category: Q101; Green_REACh: Passed
J3 = CMP-0075629-2: Header, 1.27mm, 5x2, Gold, Black, SMT; PartNumber: FTSH-105-01-F-DV; Manufacturer: Samtec; Pitch_mm: 1.27; Gender: Male; Row_Count: 2; Current_A: 3.3A; Cert_CSA: Y
L22 = CMP-0003363-1: Ferrite Bead, 220 ohm @ 100 MHz, 2 A, 0805; PartNumber: BLM21PG221SN1D; Manufacturer: MuRata; Imax_A: 2A; DCR_ohm: 0.045; Value1: 0.045 ohm; ZTyp@100MHz_Ohm: 220; SizeArea_mm2: 2.5; SizeAreaWB_mm2: 6.75; SizeX_mm: 2; SizeY_mm: 1.25; SizeZ_mm: 1.45
L23 = CMP-0003306-1: Ferrite Bead, 60 ohm @ 100 MHz, 3 A, 0805; PartNumber: BKP2125HS600-T; Manufacturer: Taiyo Yuden; Imax_A: 3A; DCR_ohm: 0.025; Value1: 0.025 ohm; ZTyp@100MHz_Ohm: 60; SizeArea_mm2: 2.5; SizeAreaWB_mm2: 6.75; SizeX_mm: 2; SizeY_mm: 1.25; SizeZ_mm: 1.45
R61 R62 = CMP-0021998-4: as R57 on sheet TIDA-050040_Battery
R63-R65 R100 = CMP-0022003-4: as R144 on sheet TIDA-050040_Battery
R66 = CMP-0021998-4: as R44 on sheet TIDA-050040_Battery
R80 = CMP-0026763-1: RES, 100, 1%, 0.063 W, AEC-Q200 Grade 0, 0402; Manufacturer: Stackpole Electronics Inc; Power_W: 63mW; TempCo: 100 ppm/C; Value_Code: 100R; U/M: EA; Value: 100; EIA_Code: E96; SizeX_mm: 1; SizeY_mm: 0.5; SizeZ_mm: 0.6; Value2: 0.063W; AEC Qualified: Y; AEC Grade: 0; AEC Category: Q200
R81-R84 = CMP-0026754-1: RES, 10.0 k, 1%, 0.063 W, AEC-Q200 Grade 0, 0402; Manufacturer: Stackpole Electronics Inc; Power_W: 63mW; TempCo: 100 ppm/C; Value_Code: 10k0; U/M: EA; Value: 10.0k; EIA_Code: E96; Res_ohm: 10k; SizeX_mm: 1; SizeY_mm: 0.5; SizeZ_mm: 0.6; Value2: 0.063W; AEC Qualified: Y; VDC_V: 50V; AEC Grade: 0; AEC Category: Q200
R85-R88 = CMP-0026759-1: RES, 33.0, 1%, 0.063 W, AEC-Q200 Grade 0, 0402; Manufacturer: Stackpole Electronics Inc; Power_W: 63mW; TempCo: 100 ppm/C; Value_Code: 33R0; U/M: EA; Value: 33.0; Res_ohm: 33; SizeX_mm: 1; SizeY_mm: 0.5; SizeZ_mm: 0.6; Value2: 0.063W; AEC Qualified: Y; VDC_V: 50V; AEC Grade: 0; AEC Category: Q200
R89 R91 R92 R94 R96 = CMP-0025697-4: RES, 0, 5%, 0.1 W, AEC-Q200 Grade 0, 0603; PartNumber: CRCW06030000Z0EA; Manufacturer: Vishay-Dale; Value: 0; Value_Code: 0000; Power_W: 100mW; Value2: 0.1W; VDC_V: 75V; TempCo: 200 ppm/C; EIA_Code: E24; AEC Category: Q200; AEC Qualified: Y; SizeArea_mm2: 1.28; SizeX_mm: 1.6; SizeY_mm: 0.8; SizeZ_mm: 1
R93 = CMP-0022986-5: RES, 2.20 k, 1%, 0.1 W, 0603; PartNumber: RC0603FR-072K2L; Manufacturer: Yageo; Value: 2.20k; Res_ohm: 2.2k; Value_Code: 2k20; Power_W: 100mW; Value2: 0.1W; VDC_V: 75V; TempCo: 100 ppm/C; AEC Category: Q200; AEC Qualified: N; SizeArea_mm2: 1.28; SizeAreaWB_mm2: 4.68; SizeX_mm: 1.6; SizeY_mm: 0.8; SizeZ_mm: 1
R95 = CMP-0023169-5: RES, 51.0, 1%, 0.1 W, 0603; Manufacturer: Yageo; Power_W: 100mW; TempCo: 100 ppm/C; Value_Code: 51R0; Value: 51.0; Res_ohm: 51; SizeX_mm: 1.6; SizeY_mm: 0.8; SizeZ_mm: 1; Value2: 0.1W; SizeArea_mm2: 1.28; AEC Qualified: N; VDC_V: 75V; AEC Category: Q200; SizeAreaWB_mm2: 4.68
R97 = CMP-0022138-4: RES, 1.00 M, 1%, 0.1 W, AEC-Q200 Grade 0, 0603; Manufacturer: Vishay-Dale; Power_W: 100mW; TempCo: 100 ppm/C; Value_Code: 1M00; Value: 1.00Meg; EIA_Code: E96; Res_ohm: 1M; SizeX_mm: 1.6; SizeY_mm: 0.8; SizeZ_mm: 1; Value2: 0.1W; SizeArea_mm2: 1.28; AEC Qualified: Y; VDC_V: 75V; AEC Category: Q200; AEC Grade: 0
R98 = CMP-0022747-4: RES, 10.0 M, 1%, 0.1 W, 0603; Manufacturer: Yageo; Power_W: 100mW; TempCo: 100 ppm/C; Value_Code: 10M0; Value: 10.0Meg; EIA_Code: E96; Res_ohm: 10M; SizeX_mm: 1.6; SizeY_mm: 0.8; SizeZ_mm: 1; Value2: 0.1W; SizeArea_mm2: 1.28; AEC Qualified: N; VDC_V: 75V; AEC Category: Q200; SizeAreaWB_mm2: 4.68
R99 R102 R103 R105 = CMP-0023341-3: RES, 10.0 k, 1%, 0.1 W, AEC-Q200 Grade 0, 0603; Manufacturer: Stackpole Electronics Inc; Power_W: 100mW; TempCo: 100 ppm/C; Value_Code: 10k0; U/M: EA; Value: 10.0k; EIA_Code: E96; Res_ohm: 10k; SizeX_mm: 1.6; SizeY_mm: 0.8; SizeZ_mm: 1; Value2: 0.1W; SizeArea_mm2: 1.28; CompType: Resistor; AEC Qualified: Y; VDC_V: 75V; AEC Grade: 0; AEC Category: Q200
R101 = CMP-0022457-4: RES, 4.87 k, 1%, 0.1 W, AEC-Q200 Grade 0, 0603; Manufacturer: Vishay-Dale; Power_W: 100mW; TempCo: 100 ppm/C; Value_Code: 4k87; Value: 4.87k; EIA_Code: E96; SizeX_mm: 1.6; SizeY_mm: 0.8; SizeZ_mm: 1; Value2: 0.1W; SizeArea_mm2: 1.28; AEC Qualified: Y; VDC_V: 75V; AEC Category: Q200; AEC Grade: 0
R104 = CMP-0027004-2: RES, 0, 5%, 0.063 W, 0402; Manufacturer: Yageo America; Power_W: 63mW; TempCo: 200 ppm/C; Value_Code: 0000; U/M: EA; Value: 0; EIA_Code: E24; SizeX_mm: 1; SizeY_mm: 0.5; SizeZ_mm: 0.6; Value2: 0.063W; CompType: Resistor; VDC_V: 50V; AEC Category: Q200
R106 = CMP-0026889-5: RES, 2.0 k, 5%, 0.063 W, AEC-Q200 Grade 0, 0402; Manufacturer: Vishay-Dale; Power_W: 63mW; TempCo: 200 ppm/C; Value_Code: 2k00; Value: 2.0k; EIA_Code: E24; Res_ohm: 2k; SizeX_mm: 1; SizeY_mm: 0.5; SizeZ_mm: 0.6; Value2: 0.063W; CompType: Resistor; AEC Qualified: Y; VDC_V: 50V; AEC Category: Q200; AEC Grade: 0
R108-R110 = CMP-0022109-5: as R134 on sheet TIDA-050040_Battery
TP1 = CMP-0055152-1: Test Point, Miniature, SMT; Manufacturer: Keystone; CNHeader: FALSE; Green_Lifecycle: Active; Green_REACh: Passed; CT: TRUE
U3 = CMP-0079113-2: Local Interconnect Network (LIN) Transceiver with Dominant State Timeout, D0008A (SOIC-8); Alternate Manufacturer: Texas Instruments; Alternate PartNumber: TLIN1029DQ1; CompType: IC; SizeX_mm: 4.9; AEC Category: Q200; SizeArea_mm2: 30.38; SizeZ_mm: 1.75; SizeY_mm: 6.2; SizeAreaWB_mm2: 56.58; AEC Qualified: Y
U10 = CMP-0077953-1: MSP432E401YTPDT, PDT0128A (TQFP-128); Alternate PartNumber: MSP432E401YTPDTR; Alternate Manufacturer: Texas Instruments; SizeAreaWB_mm2: 324; SizeZ_mm: 1.2; SizeX_mm: 16; SizeArea_mm2: 256; CompType: IC; AEC Qualified: N; AEC Category: Q200
Y1 = CMP-0004653-5: Crystal, 32.768 kHz,  SMD; Manufacturer: Citizen FineDevice; TaMin_C: -40°C; Frequency Stability: +/-20ppm; TaMax_C: 85°C; AEC Category: Q200; AEC Qualified: N
Y2 = CMP-0004652-3: Crystal, 25 MHz, 8pF, SMD; Manufacturer: NDK; TaMax_C: 85°C; TaMin_C: -40°C; Frequency Stability: +/-30ppm; Frequency_Fixed: 25MHz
